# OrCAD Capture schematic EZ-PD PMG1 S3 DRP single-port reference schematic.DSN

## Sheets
1 01. TITLE AND CONTENTS: title: PMG1-S3 (CYPM1311) DRP REFERENCE DESIGN; rev: 01; note: XXX-xxxxx-xx
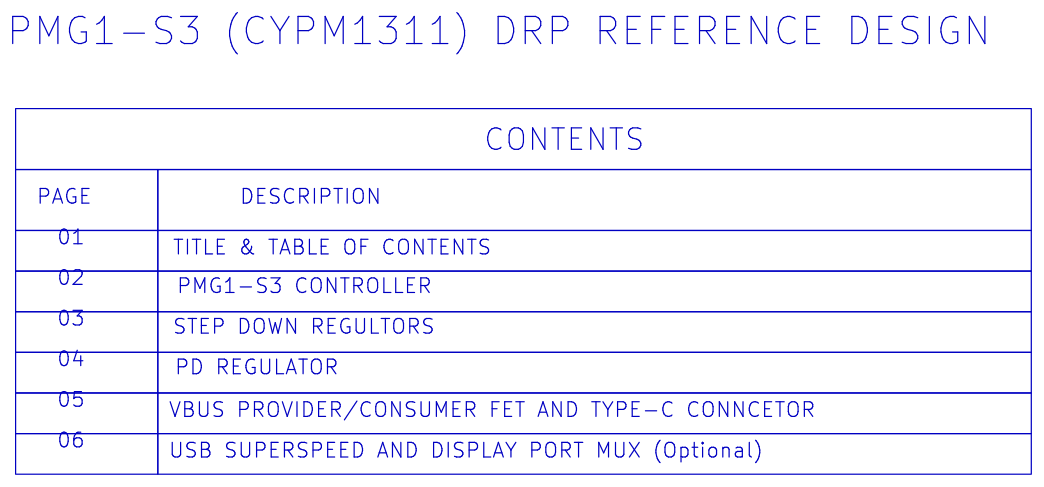
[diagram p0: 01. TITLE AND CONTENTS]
2 05. PROVIDER AND CONSUMER PATH: size A4
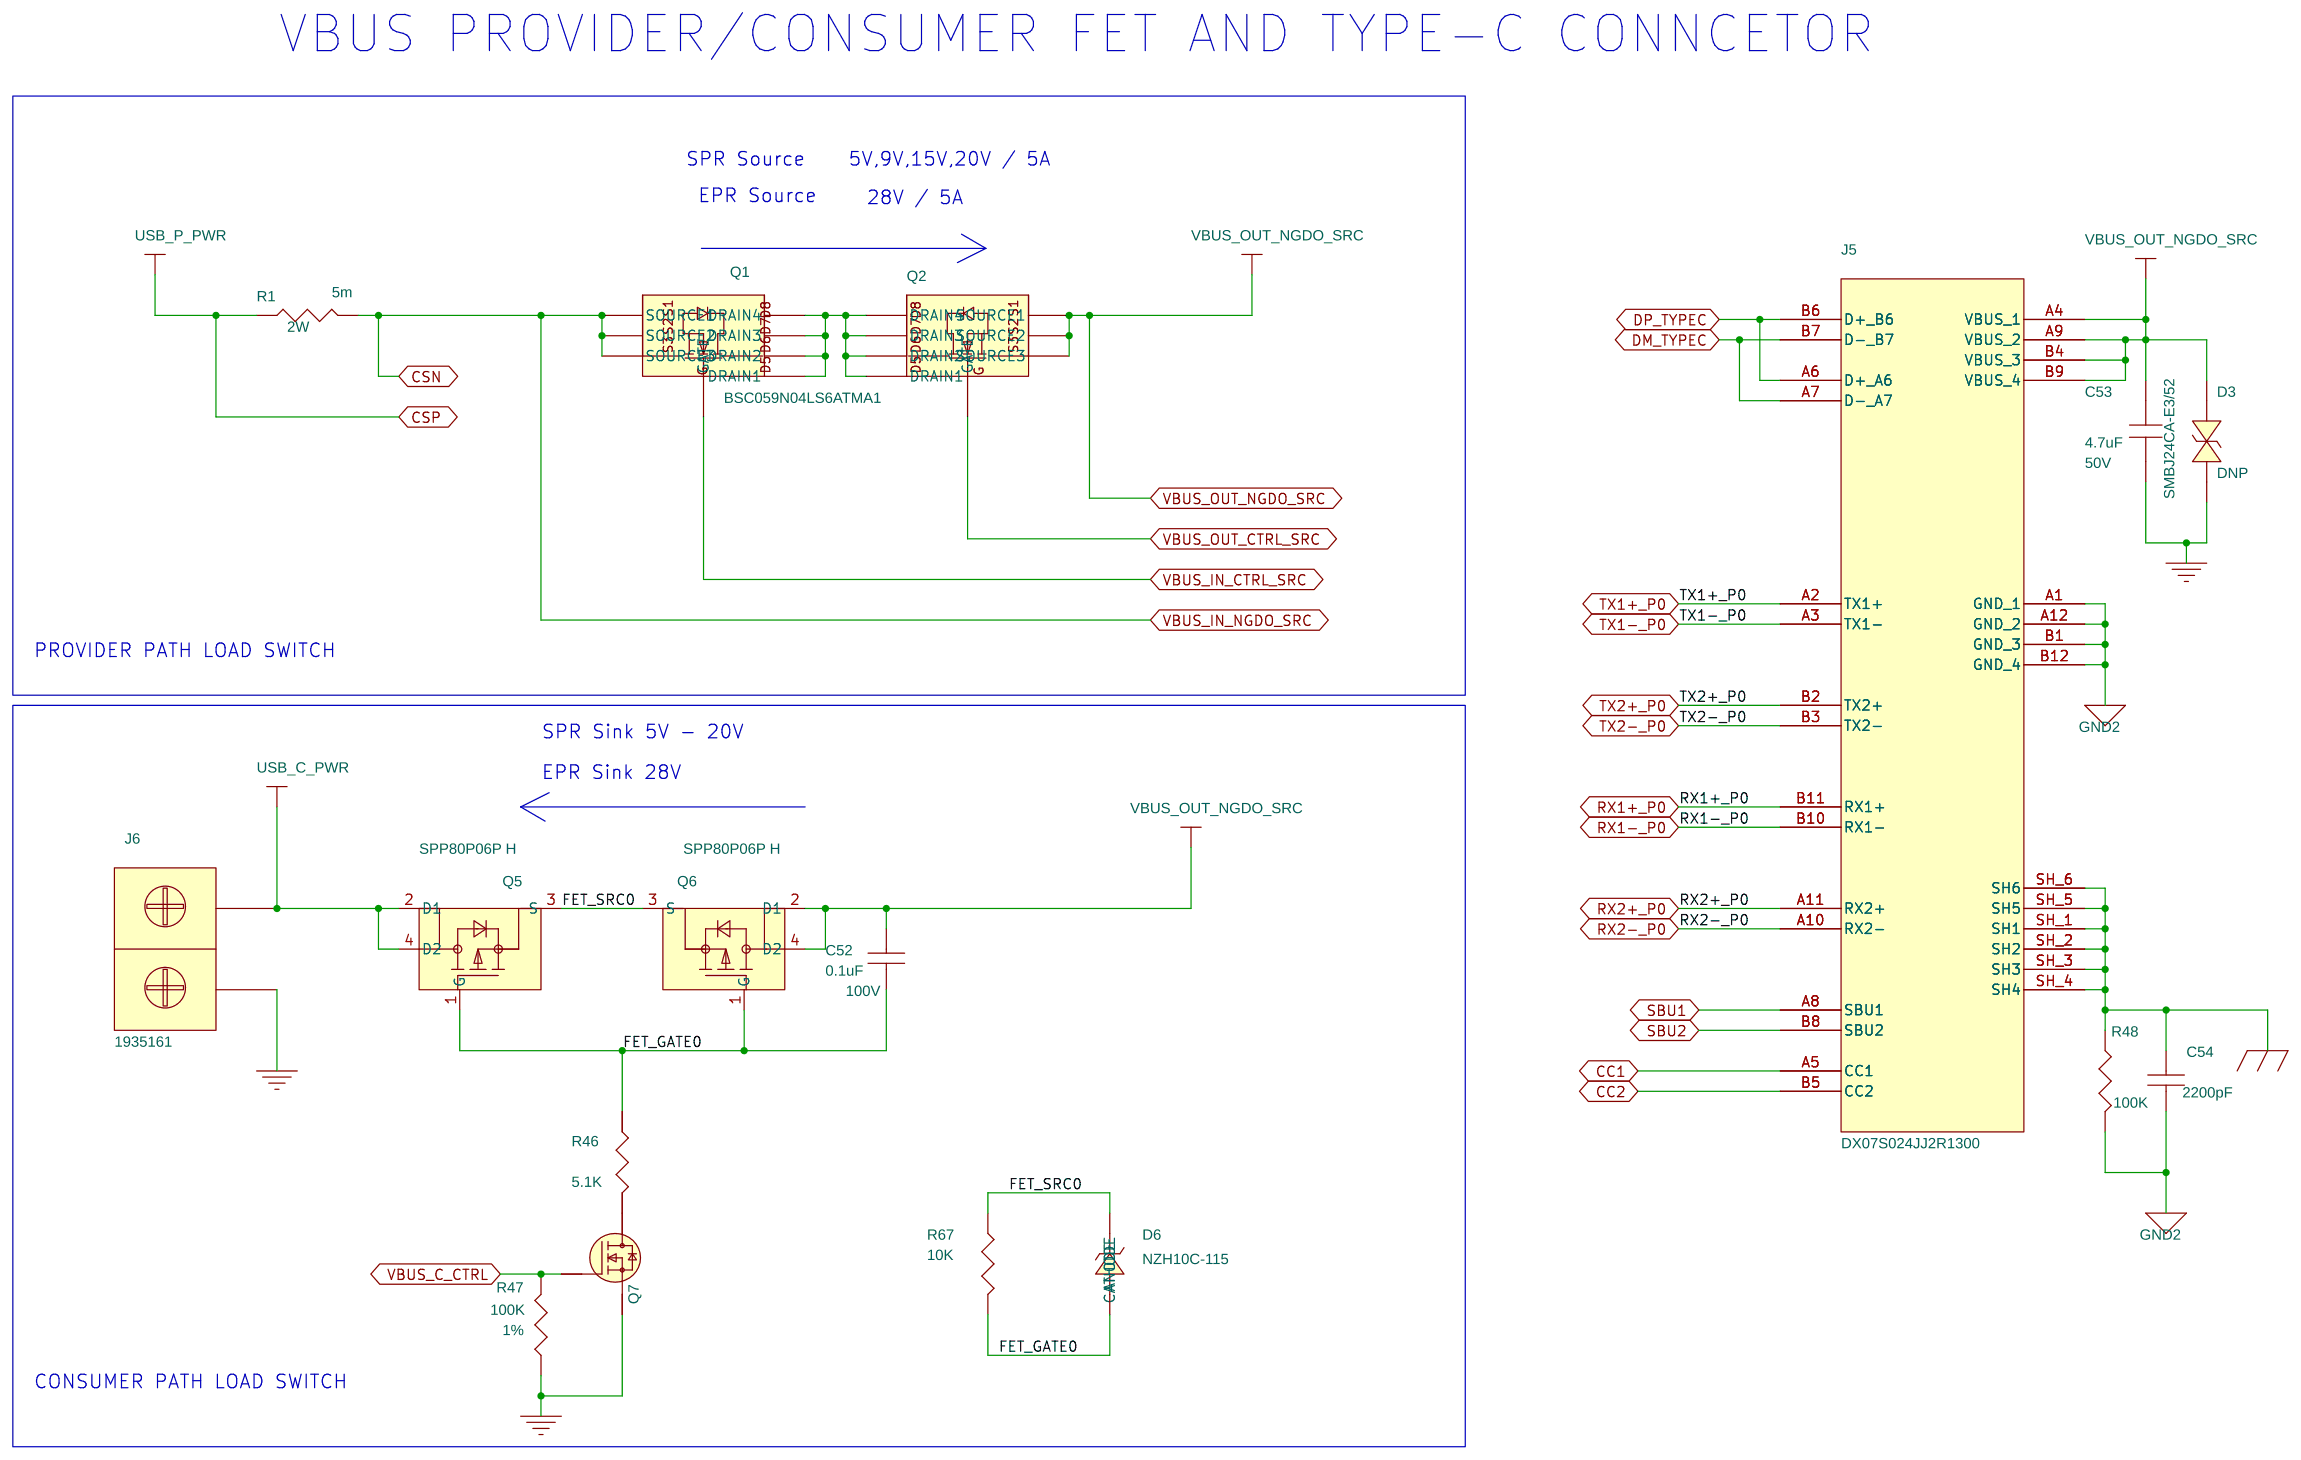
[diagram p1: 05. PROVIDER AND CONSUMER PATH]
3 06. USB SUPERSPEED AND DISPLAY: size A4
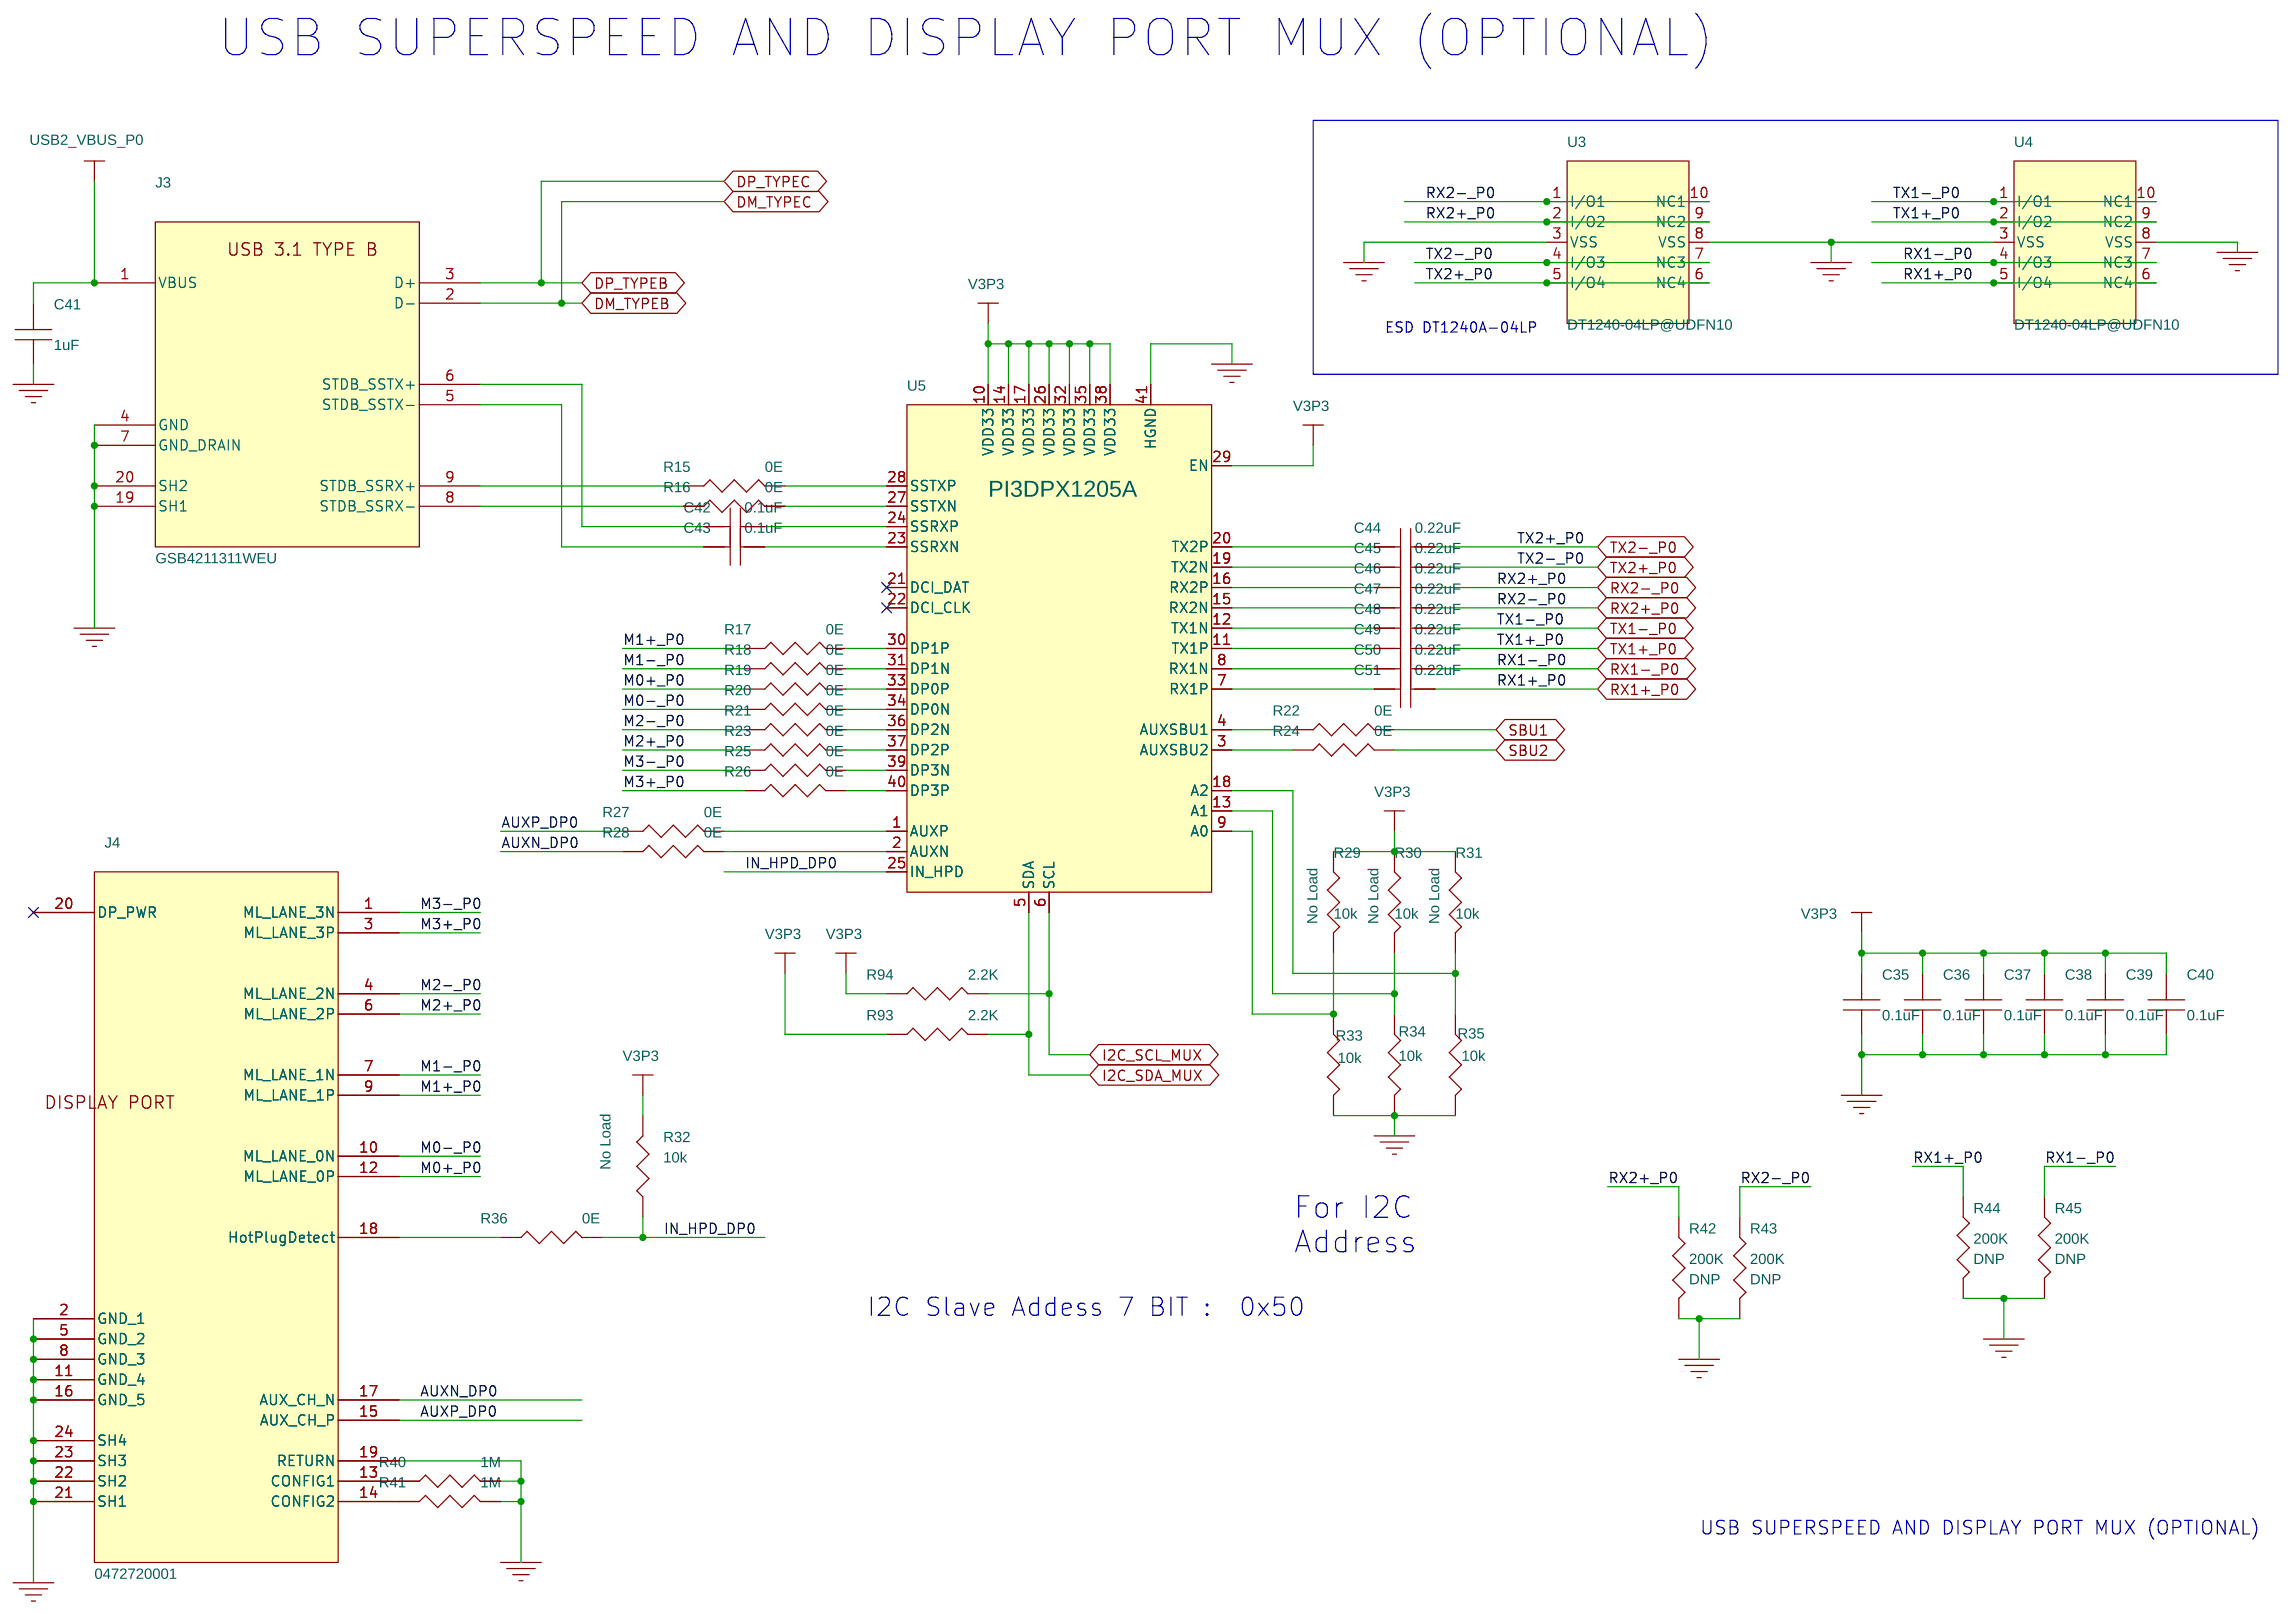
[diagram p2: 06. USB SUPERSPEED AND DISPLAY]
4 04. PD REGULATOR: size A4
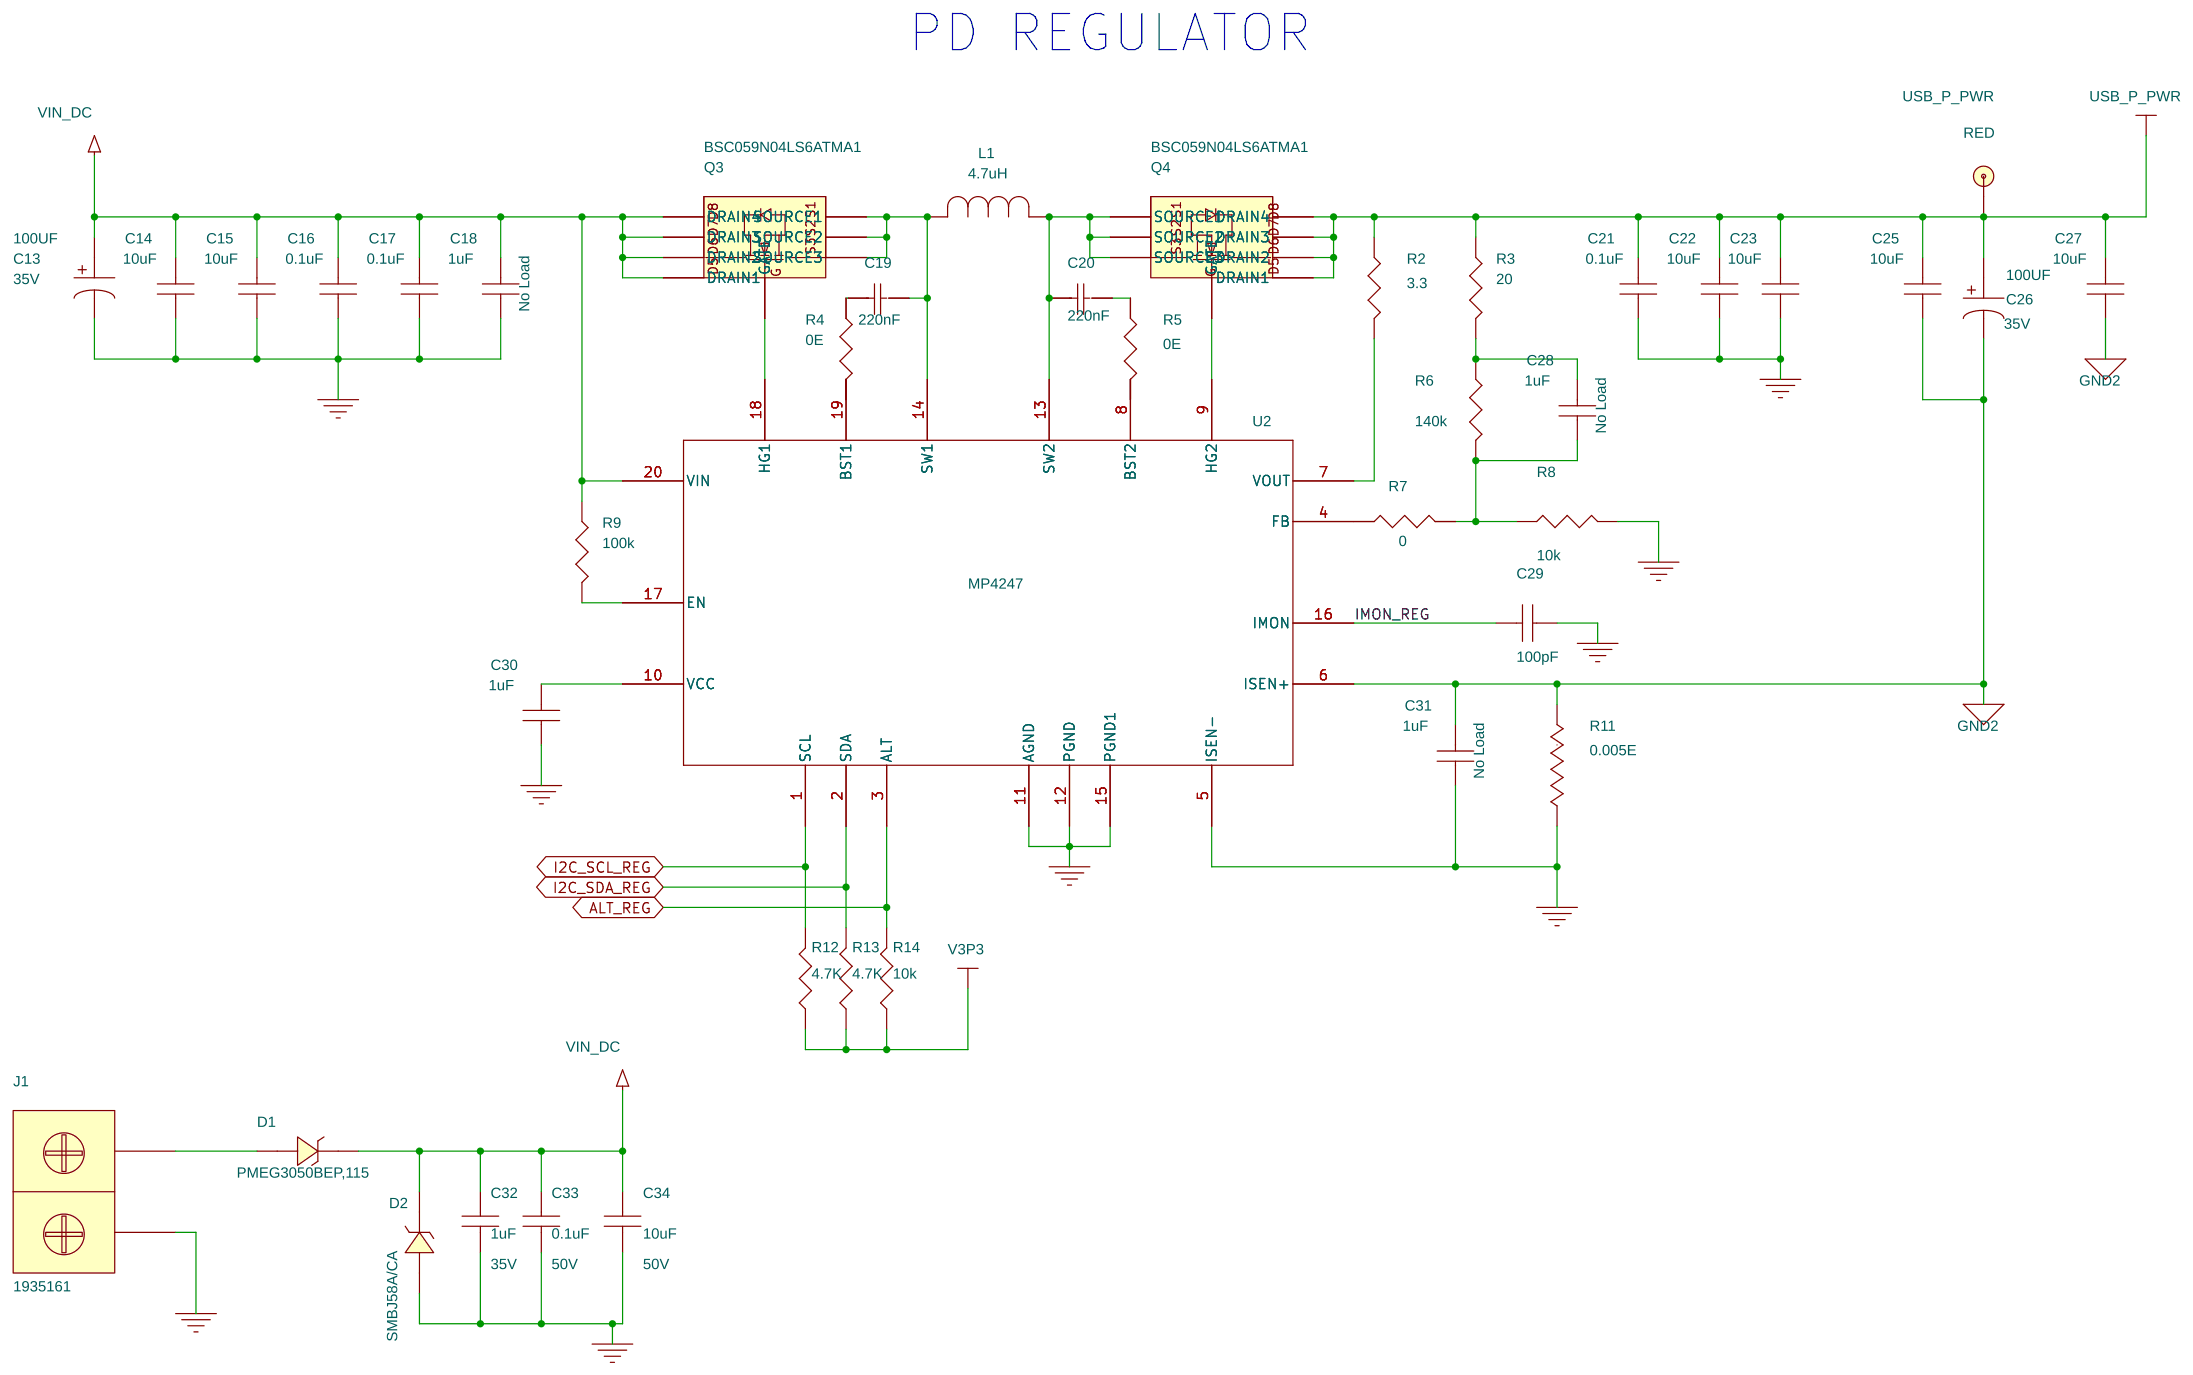
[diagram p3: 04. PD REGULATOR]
5 03. STEP DOWN REGULATORS: size A4
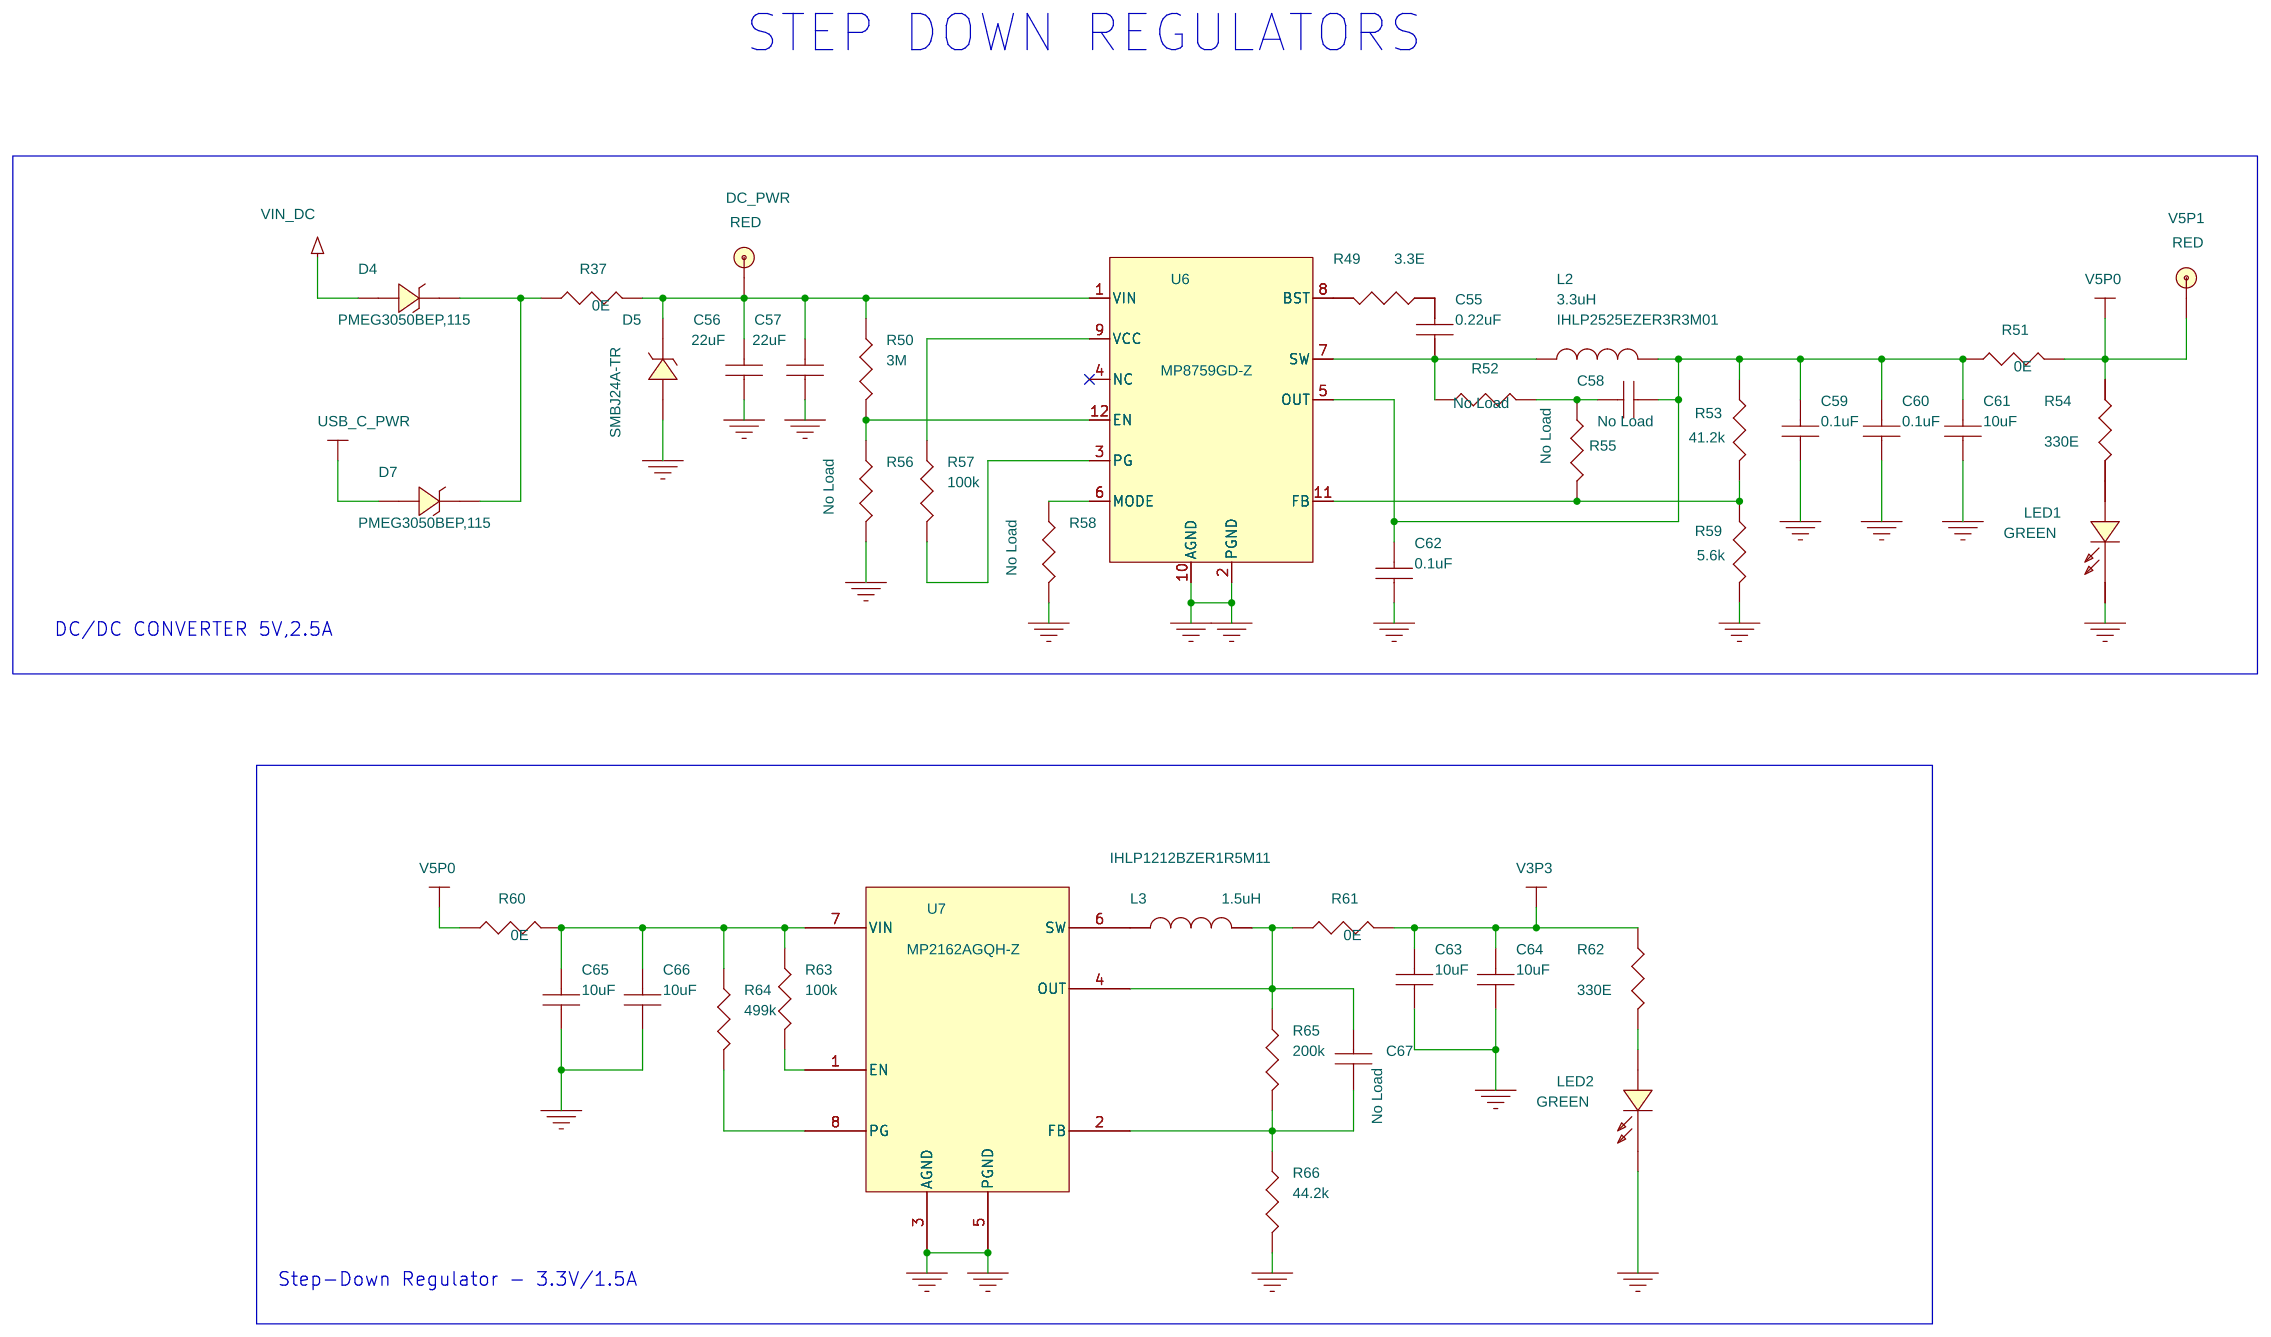
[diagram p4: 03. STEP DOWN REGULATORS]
6 02. PMG1-S3: size A4
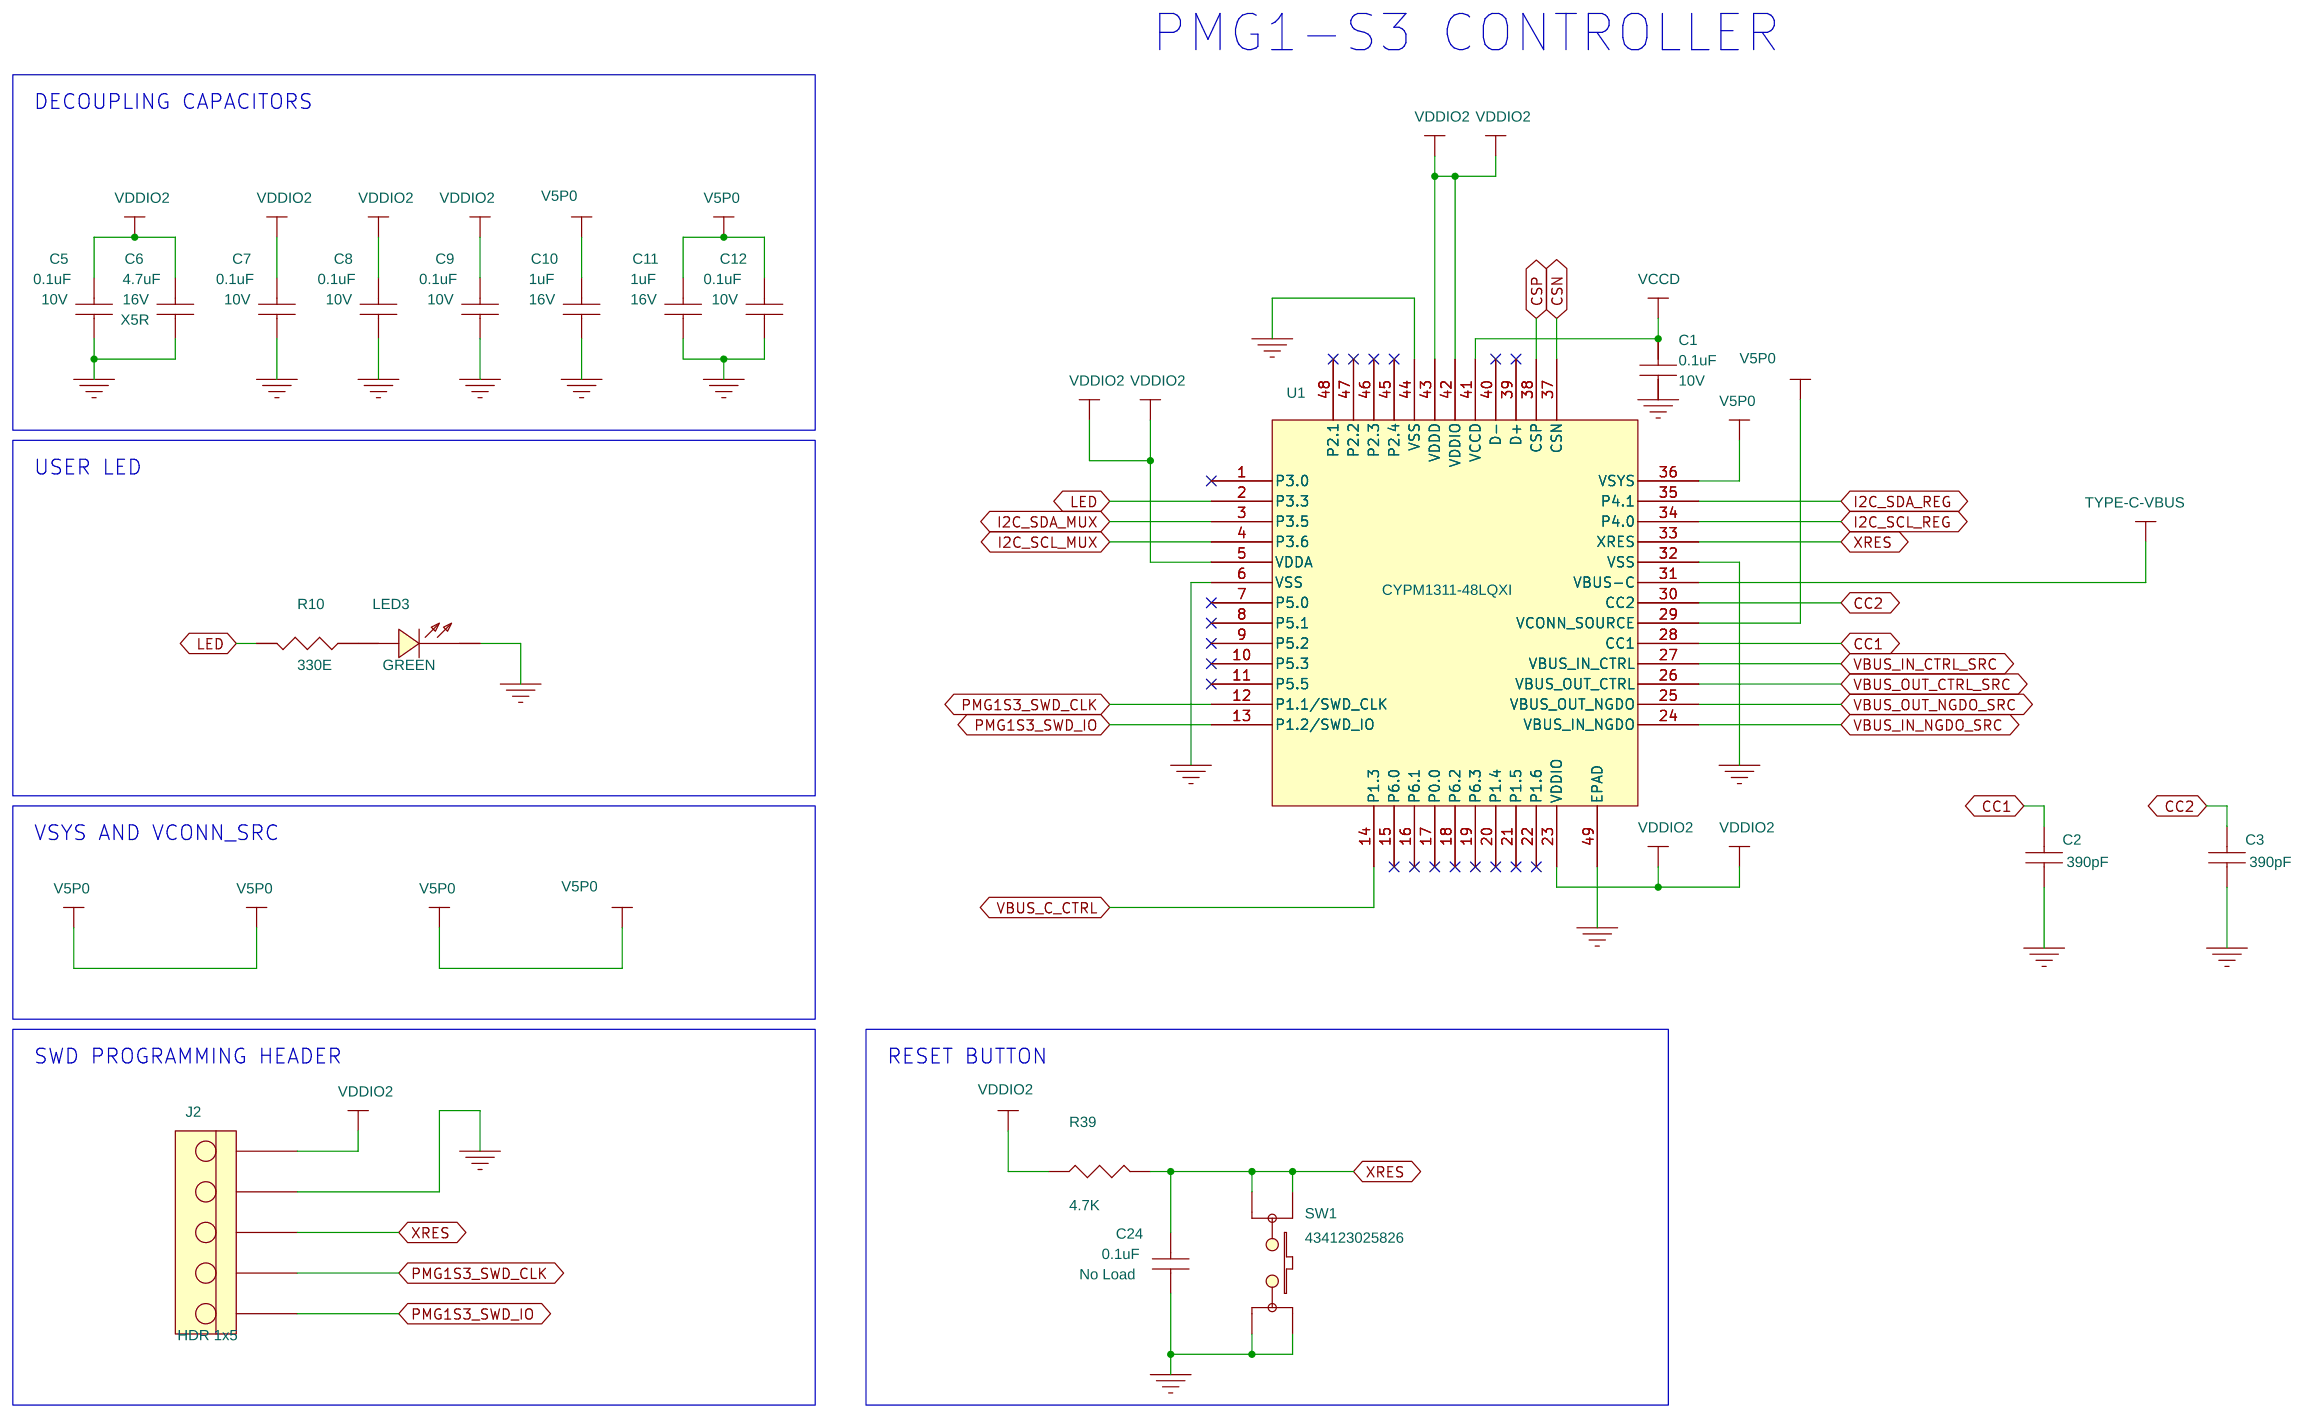
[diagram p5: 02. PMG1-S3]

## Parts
sheet 02. PMG1-S3
C1  0.1uF  [CAPC1005_0402N]
C2  390pF  [capc1608x90n_ty]
C3  390pF  [capc1608x90n_ty]
C5  0.1uF  [CAPC1005_0402N]
C6  4.7uF  [capc1608x90n_ty]
C7  0.1uF  [CAPC1005_0402N]
C8  0.1uF  [CAPC1005_0402N]
C9  0.1uF  [CAPC1005_0402N]
C10  1uF  [capc1608x90n_ty]
C11  1uF  [capc1608x90n_ty]
C12  0.1uF  [CAPC1005_0402N]
C24  0.1uF  [CAPC1005_0402N]
J2  HDR 1x5  [HDR5_KEYED_M]
LED3  GREEN  [LEDC1608X80N_G]
R10  330E  [RESC1608X55N_A]
R39  4.7K  [RESC1005_0402M]
SW1  434123025826  [SW_SKRPACE010]
U1  CYPM1311-48LQXI  [QFN40P600X600X60-49N]
sheet 03. STEP DOWN REGULATORS
C55  0.22uF  [capc1608x90n_ty]
C56  22uF  [CAPC3216X180N]
C57  22uF  [CAPC3216X180N]
C58  0.22uF  [capc1608x90n_ty]
C59  0.1uF  [capc1608x90n_ty]
C60  0.1uF  [capc1608x90n_ty]
C61  10uF  [capc1608x90n_ty]
C62  0.1uF  [capc1608x90n_ty]
C63  10uF  [capc1608x90n_ty]
C64  10uF  [capc1608x90n_ty]
C65  10uF  [capc1608x90n_ty]
C66  10uF  [capc1608x90n_ty]
C67  0.22uF  [capc1608x90n_ty]
D4  PMEG3050BEP,115  [SOD128]
D5  SMBJ24A-TR  [SMBJ24A-TR]
D7  PMEG3050BEP,115  [SOD128]
DC_PWR  RED  [TP-43R_S]
L2  3.3uH  [IHLP2525EZER3R3M01]
L3  1.5uH  [IHLP1212BZER1R5M11]
LED1  GREEN  [LEDC1608X80N_G]
LED2  GREEN  [LEDC1608X80N_G]
R37  0E  [RESC2012X70N_PEC]
R49  3.3E  [resc1608x55n_pec]
R50  3M  [resc1005x40n_pec]
R51  0E  [RESC2012X70N_PEC]
R52  0E  [resc1608x55n_pec]
R53  41.2k  [resc1608x55n_pec]
R54  330E  [resc1608x55n_pec]
R55  0E  [resc1608x55n_pec]
R56  R  [resc1005x40n_pec]
R57  100k  [resc1005x40n_pec]
R58  R  [resc1005x40n_pec]
R59  5.6k  [resc1608x55n_pec]
R60  0E  [RESC2012X70N_PEC]
R61  0E  [RESC2012X70N_PEC]
R62  330E  [resc1608x55n_pec]
R63  100k  [resc1005x40n_pec]
R64  499k  [resc1005x40n_pec]
R65  200k  [resc1005x40n_pec]
R66  44.2k  [resc1005x40n_pec]
U6  MP8759GD-Z  [QFN12_2X3mm]
U7  MP2162AGQH-Z  [QFN8_2P0X1P5]
V5P1  RED  [TP-43R_S]
sheet 04. PD REGULATOR
C13  100UF  [CAPAE830X900D900DD320N]
C14  10uF  [capc1608x90n_ty]
C15  10uF  [capc1608x90n_ty]
C16  0.1uF  [capc1608x90n_ty]
C17  0.1uF  [capc1608x90n_ty]
C18  1uF  [capc1608x90n_ty]
C19  CAP\0603  [CAP_0402]
C20  CAP\0603  [CAP_0402]
C21  0.1uF  [capc1608x90n_ty]
C22  10uF  [capc1608x90n_ty]
C23  10uF  [capc1608x90n_ty]
C25  10uF  [capc1608x90n_ty]
C26  100UF  [CAPAE830X900D900DD320N]
C27  10uF  [capc1608x90n_ty]
C28  1uF  [capc1608x90n_ty]
C29  100pF  [capc1608x90n_ty]
C30  1uF  [capc1005x56n_cyps]
C31  1uF  [capc1608x90n_ty]
C32  1uF  [capc1608x90n_ty]
C33  0.1uF  [capc1005x56n_cyps]
C34  10uF  [capc3225x280n_tdk]
D1  PMEG3050BEP,115  [SOD128]
D2  SMBJ58A/CA  [SMBJ24A-TR]
J1  1935161  [1935161]
L1  TOKO106C_L1  [inductor_adjust]
Q3  BSC059N04LS6ATMA1  [BSC059N04LS6ATMA1]
Q4  BSC059N04LS6ATMA1  [BSC059N04LS6ATMA1]
R2  3.3  [resc1005x40n_pec]
R3  20  [resc1608x55n_pec]
R4  0E  [resc1005x40n_pec]
R5  0E  [resc1005x40n_pec]
R6  140k  [resc1608x55n_pec]
R7  0  [resc1608x55n_pec]
R8  10k  [resc1608x55n_pec]
R9  100k  [resc1608x55n_pec]
R11  0.005E  [WSL1206]
R12  4.7K  [resc1608x55n_pec]
R13  4.7K  [resc1608x55n_pec]
R14  10k  [resc1608x55n_pec]
U2  MP4247  [QFN20]
USB_P_PWR  RED  [TP-43R_S]
sheet 05. PROVIDER AND CONSUMER PATH
C52  0.1uF  [capc1005x56n_cyps]
C53  4.7uF  [capc3225x280n_tdk]
C54  2200pF  [C1808]
D3  SMBJ24CA-E3/52  [SMBJ24CA_3P679_2H44]
D6  NZH10C-115  [SOD123F_NZH10C-115]
J5  DX07S024JJ2R1300  [USB-PD_TYPE-C]
J6  1935161  [1935161]
Q1  BSC059N04LS6ATMA1  [BSC059N04LS6ATMA1]
Q2  BSC059N04LS6ATMA1  [BSC059N04LS6ATMA1]
Q5  SPP80P06P H
Q6  SPP80P06P H
Q7  2N7002LT1G  [SOT23_2N7002LT1G]
R1  5m  [RESC6432X69N]
R46  5.1K  [resc1005x40n_pec]
R47  100K  [resc1608x55n_pec]
R48  100K  [resc1005x40n_pec]
R67  10K  [resc1005x40n_pec]
sheet 06. USB SUPERSPEED AND DISPLAY
C35  0.1uF  [capc1005x56n_cyps]
C36  0.1uF  [capc1005x56n_cyps]
C37  0.1uF  [capc1005x56n_cyps]
C38  0.1uF  [capc1005x56n_cyps]
C39  0.1uF  [capc1005x56n_cyps]
C40  0.1uF  [capc1005x56n_cyps]
C41  1uF  [capc1005x56n_cyps]
C42  0.1uF  [capc1005x56n_cyps]
C43  0.1uF  [capc1005x56n_cyps]
C44  0.22uF  [capc1005x56n_cyps]
C45  0.22uF  [capc1005x56n_cyps]
C46  0.22uF  [capc1005x56n_cyps]
C47  0.22uF  [capc1005x56n_cyps]
C48  0.22uF  [capc1005x56n_cyps]
C49  0.22uF  [capc1005x56n_cyps]
C50  0.22uF  [capc1005x56n_cyps]
C51  0.22uF  [capc1005x56n_cyps]
J3  GSB4211311WEU  [USB_CONN_GSB3211311WEU]
J4  0472720001  [CONN20_0472720001]
R15  0E  [resc1005x40n_pec]
R16  0E  [resc1005x40n_pec]
R17  0E  [resc1005x40n_pec]
R18  0E  [resc1005x40n_pec]
R19  0E  [resc1005x40n_pec]
R20  0E  [resc1005x40n_pec]
R21  0E  [resc1005x40n_pec]
R22  0E  [resc1005x40n_pec]
R23  0E  [resc1005x40n_pec]
R24  0E  [resc1005x40n_pec]
R25  0E  [resc1005x40n_pec]
R26  0E  [resc1005x40n_pec]
R27  0E  [resc1005x40n_pec]
R28  0E  [resc1005x40n_pec]
R29  10k  [resc1608x55n_pec]
R30  10k  [resc1608x55n_pec]
R31  10k  [resc1608x55n_pec]
R32  10k  [resc1005x40n_pec]
R33  10k  [resc1608x55n_pec]
R34  10k  [resc1608x55n_pec]
R35  10k  [resc1608x55n_pec]
R36  0E  [resc1608x55n_pec]
R40  1M  [resc1005x40n_pec]
R41  1M  [resc1005x40n_pec]
R42  200K  [RESC1005X40N_PEC]
R43  200K  [RESC1005X40N_PEC]
R44  200K  [RESC1005X40N_PEC]
R45  200K  [RESC1005X40N_PEC]
R93  2.2K  [RESC2012X70N_PEC]
R94  2.2K  [RESC2012X70N_PEC]
U3  DT1240-04LP@UDFN10  [DT1240-04LP-7_10DFN]
U4  DT1240-04LP@UDFN10  [DT1240-04LP-7_10DFN]
U5  PI3DPX1205A  [QFN40P400X600X80-41T475X275N]

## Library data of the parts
C1 C5 C7-C9 C12 = CAP_NP: CAP CER 0.1UF 10V X7R 0402; Manufacturer: AVX Corporation; Mfr_Name: AVX Corporation; Mfr_Part#: 0402ZC104KAT2A; RATED_VOLTAGE: 10V; Rating: 10V; SIGNAL_MODEL: DEFAULT_CAPACITOR_1pF_1_2; Temp_Coefficient: X7R; Tolerance: 10%; VOLTAGE: 10V
C2 C3 = CAP-NP_0: CAP CER 390PF 50V 5% X7R 0603; Manufacturer: Kemet; Mfr_Name: Kemet; Mfr_Part#: C0603C391J5RACTU; RATED_VOLTAGE: 10V; Temp_Coefficient: X7R; Tolerance: 5%; VOLTAGE: 50V
C6 = CAP-NP_0: CAP CER 4.7UF 16V X5R 0603; Manufacturer: Samsung Electro-Mechanics; Mfr_Name: Samsung Electro-Mechanics; Mfr_Part#: CL10A475KO8NNNC; RATED_VOLTAGE: 16V; Temp_Coefficient: X5R; Tolerance: 10%; VOLTAGE: 16V
C10 C11 = CAP-NP_0: CAP CER 1UF 16V X7R 0603; Manufacturer: KEMET; Mfr_Name: KEMET; Mfr_Part#: C0603C105K4RACTU; RATED_VOLTAGE: 16V; Temp_Coefficient: X7R; Tolerance: 10%; VOLTAGE: 16V
C24 = CAPACITOR_NON-POL: CAP CER 0.1UF 16V X7R 0402; Asm_Instruction: No Load; Cy_Part#: 510-60247-01; Manufacturer: Würth Elektronik; Mfr_Name: Wurth; Mfr_Part#: 885012205037; Tolerance: 10%; VOLTAGE: 16V
J2 = 1X5_100MIL_HDR_4: CONN HEADER 5POS 0.1 VERT KEYED; MFG Part number: 22232051; Manufacturer: Molex, LLC; Mfr_Name: Molex; Mfr_Part#: 22232051; Mfr_Part_Number: 22-23-2051; PART_NUMBER: 22232051
LED3 = LED_GREEN2_0603: LED GREEN CLEAR 0603 SMD; Manufacturer: Lite-On Inc.; Manufacturer Part Num: 160-1183-6-ND; Mfr_Name: Lite-On Inc.; Mfr_Part#: LTST-C190GKT
R10 = RESD,0402,5%,1_32W,10K: RES SMD 330 OHM 5% 1/10W 0603; IPN: D66113-001; Manufacturer: Yageo; Mfg2: Yageo; Mfr_Name: Yageo; Mfr_Part#: RC0603JR-07330RL; Tolerance: 5%; Wattage: 1/10W
R39 = RESISTOR: RES, 4.7K OHM, 5%, 100PPM, 1/16W, 0402; Cy_part#: 500-60095-01; Manufacturer: Yageo; Mfr_Name: Yageo; Mfr_Part#: RC0402JR-074K7L; Tolerance: 5%
SW1 = SW_PUSH_NO_4-PIN: SW, TACTILE SWITCH, 4.2x3.2x2.5MM, 260GF; Cy_part#: 770-60033-01; Manufacturer: Würth Elektronik; Mfr_Name: Wurth
U1 = CYPM1311-48LQXI_0: Manufacturer: CYPRESS; Mfr_Name: CYPRESS
C55 = CAP-NP_0: CAP CER 0.22UF 10V X7R 0603; Manufacturer: YAGEO; Mfr_Part#: CC0603KRX7R6BB224
C56 C57 = CAP-NP_0: CAP CER 22UF 35V X5R 1206; Manufacturer: TDK Corporation; Mfr_Part#: C3216X5R1V226M160AC
C58 C67 = CAP-NP_0: CAP CER 0.22UF 10V X7R 0603; Asm_Instruction: No Load; Manufacturer: YAGEO; Mfr_Part#: CC0603KRX7R6BB224
C16 C17 C21 C59 C60 C62 = CAP-NP_0: CAP CER 0.1UF 10V X7R 0603; Manufacturer: Kemet; Mfr_Part#: C0603C104K8RACTU
C14 C15 C22 C23 C25 C27 C61 C63-C66 = CAP-NP_0: CAP CER 10UF 10V 10% X5R 0603; Manufacturer: TDK Corporation; Mfr_Part#: C1608X5R1A106K080AC
D1 D4 D7 = BZX84C18_SOT_0: DIODE SCHOTTKY 30V 5A SOD128; Cypress Part No: 530-60089-01; Manufacturer: NXP Semiconductors
D2 D5 = BZX84C18_SOT_0: TVS DIODE 24VWM 50VC DO214AA; Cypress Part No: 530-60092-01; Manufacturer: STMicroelectronics
DC_PWR USB_P_PWR V5P1 = TEST_POINT: TEST POINT PC MINI .040"D RED; Cypress Part No: 711-60001-01; Manufacturer: Keystone Electronics; Mfr_Part#: 5001
L2 = INDUCTOR: FIXED IND 3.3UH 8A 20.9 MOHM SMD; Cost: .01; Manufacturer: Vishay Dale; Tolerance: NA; Voltage: NA
L3 = INDUCTOR: FIXED IND 1.5UH 3.8A 32 mOHM SMD; Cost: .01; Manufacturer: Vishay Dale; Tolerance: NA; Voltage: NA
LED1 LED2 = LED_GREEN2_0: LED GREEN CLEAR 0603 SMD; Cypress Part No: 534-60005-01; MFG Part number: LTST-C190GKT; Manufacturer: Lite-On Inc.; Mfr_Part#: LTST-C190GKT
R37 R51 R60 R61 = R: RES 0 OHM JUMPER 1/8W 0805; Manufacturer: YAGEO; Mfr_Part#: RC0805JR-070RL
R49 = R: RES SMD 3.3 OHM 5% 1/10W 0603; Manufacturer: Panasonic Electronic Components; Mfr_Part#: ERJ-3GEYJ3R3V
R50 = R: RES 3M OHM 5% 1/16W 0402; Manufacturer: YAGEO; Mfr_Part#: RC0402JR-073ML
R52 R55 = R: RES 0 OHM JUMPER 1/10W 0603; Asm_Instruction: No Load; Manufacturer: YAGEO; Mfr_Part#: RC0603FR-070RL
R53 = R: RES 41.2K OHM 1% 1/10W 0603; Manufacturer: YAGEO; Mfr_Part#: RC0603FR-0741K2L
R54 R62 = R: RES SMD 330 OHM 5% 1/10W 0603; Manufacturer: YAGEO; Mfr_Name: YAGEO; Mfr_Part#: RC0603JR-07330RL; Wattage: 1/10W
R56 R58 = R: Asm_Instruction: No Load
R57 R63 = R: RES SMD 100K OHM 1% 1/5W 0402; MFG Part number: RCS0402100KFKED; Manufacturer: Vishay Dale; Mfr_Part#: RCS0402100KFKED
R59 = R: RES 5.6K OHM 5% 1/10W 0603; Manufacturer: YAGEO; Mfr_Part#: RC0603JR-075K6L
R64 = R: RES 499K OHM 0.1% 1/16W 0402; Manufacturer: YAGEO; Mfr_Part#: RC0402BR-07499KL
R65 = R: RES SMD 200K OHM 1% 1/10W 0402; MFG Part number: ERJ-2RKF2003X; Manufacturer: Panasonic Electronic Components; Mfr_Part#: ERJ-2RKF2003X
R66 = R: RES 44.2K OHM 1% 1/16W 0402; Manufacturer: YAGEO; Mfr_Part#: RC0402FR-0744K2L
U6 = mp8759_0: IC SYNC BUCK CONVERTER 8A 26V; Manufacturer: MPS
U7 = MP2162_1: IC REG BUCK ADJ 2A SYNC QFN; Manufacturer: MPS
C13 C26 = CAP_TH_Rad_8mmDia_3_5mmPitch: CAP ALUM POLY 100UF 20% 35V SMD; MFG Part number: RHS1V101MCN1GS; Manufacturer: Nichicon; Mfr_Name: Nichicon; Mfr_Part#: RHS1V101MCN1GS; Voltage: 35V
C18 C28 C31 = CAP-NP_0: CAP CER 1UF 35V X7R 0603; Asm_Instruction: No Load; Manufacturer: TDK Corporation; Mfr_Part#: C1608X7R1V105K080AC
C19 = CAP0603_C3: User_Value: 220nF
C20 = CAP0603_C4: User_Value: 220nF
C29 = CAP-NP_0: CAP CER 100PF 50V C0G 0603; Manufacturer: TDK Corporation; Mfr_Part#: C1608C0G1H101J080AA
C30 = CAP-NP_0: CAP CER 0.1UF 10V X7R 0402; Alternate Manufacturer: Samsung Electro-Mechanics; Alternate Mfr Part #: CL05B104KP5NNNC; Manufacturer: TDK Corporation; Mfr_Part#: C1005X7R1A104K050BB
C32 = CAP_NP: CAP CER 1UF 35V X7R 0603; Cypress Part No: 510-60420-01; MFG Part number: C1608X7R1V105K080AC; Manufacturer: TDK Corporation; Mfr_Part#: C1608X7R1V105K080AC; VOLTAGE: 35V
C33 = CAP_NP: CAP CER 0.1UF 25V X7R 0402; Alternate Manufacturer: Samsung Electro-Mechanics; Alternate Mfr Part #: CL05B104KP5NNNC; Manufacturer: TDK Corporation; Mfr_Part#: C1005X7R1H104K050BB; Voltage: 50V
C34 = CAP_NP: CAP CER 10UF 50V X7R 1210; Cypress Part No: 510-60333-01; MFG Part number: CL32B106KBJNNWE; Manufacturer: Samsung Electromechanics; Mfr Prt #: CL32B106KBJNNWE; Mfr_Part#: CL32B106KBJNNWE; VOLTAGE: 50V
J1 J6 = TERMINAL_BLOCK: TERM BLOCK PCB 2POS 5.0MM GREEN; Cypress Part No: 720-60276-01; Manufacturer: Phoenix Contact
L1 = TOKO106C_L1: User_Value: 4.7uH
Q1-Q4 = BSC059N04LS_G_2: MOSFET N-CH 40V 17A TDSON; Manufacturer: Infineon Technologies; Mfr_Name: Infineon Technologies
R2 = RESISTOR: RES SMD 3.3 OHM 1% 1/16W 0402; DIGI-KEY PART NO: 541-0.0JCT-ND; MFG Part number: CRCW04023R30FKED; Manufacturer: Vishay Dale; Manufaturer: Vishay Dale; Mfr_Part#: CRCW04023R30FKED; Price: 0.074
R3 = R: RES SMD 20 OHM 5% 1/10W 0603; Manufacturer: Vishay Dale; Mfr_Part#: CRCW060320R0JNEA
R4 R5 = RESISTOR: RES 0.0 OHM 1/16W JUMP 0402 SMD; DIGI-KEY PART NO: 541-0.0JCT-ND; MFG Part number: CRCW04020000Z0ED; Manufacturer: Vishay Dale; Mfr_Part#: CRCW04020000Z0ED; Price: 0.074
R6 = R: RES 140K OHM 1% 1/10W 0603; Manufacturer: YAGEO; Mfr_Part#: RC0603FR-07140KL
R7 R36 = R: RES 0 OHM JUMPER 1/10W 0603; Manufacturer: YAGEO; Mfr_Part#: RC0603FR-070RL
R8 R14 R33-R35 = R: RES 10K OHM 5% 1/10W 0603; Manufacturer: YAGEO; Mfr_Part#: RC0603JR-1010KL
R9 = R: RES SMD 100K OHM 1% 1/10W 0603; MFG Part number: ERJ-3EKF1003V; Manufacturer: PANASONIC ELECTRONIC COMPONENTS; Mfr_Part#: ERJ-3EKF1003V
R11 = Resistor_1206_Generic_SMD_4: 0.005 Ohms 1 %  1/2 W 1206 SMD; MFG: Vishay; MFG Part number: WSL12065L000FEA18; Manufacturer: Vishay Dale; Mfr_Part#: WSL12065L000FEA18; Package: 1206; Wattage: 1/2 W
R12 R13 = R: RES 4.7K OHM 5% 1/10W 0603; Manufacturer: RC0603JR-074K7L; Mfr_Part#: RC0603JR-074K7L
U2 = MPQ4260_U1_0: Buck-boost converter with lowside MOSFETs; MFG Part number: MP4247GQV; Manufacturer: Monolithic Power Systems; Mfr_Part#: MP4247GQV
C52 = CAP_NP: CAP CER 0.1UF 25V X7R 0402; Alternate Manufacturer: Samsung Electro-Mechanics; Alternate Mfr Part #: CL05B104KP5NNNC; Manufacturer: TDK Corporation; Mfr_Part#: C1005X7R1A104K050BB; Voltage: 100V
C53 = 10uF-50V-10%-X5R-1206: CAP CER 4.7UF 50V X7R 1210; Cypress Part No: 510-60425-01; MFG Part number: GRJ32ER71H475KE11L; Manufacturer: Murata Electronics North America; Mfr_Part#: GRJ32ER71H475KE11L; Voltage: 50V
C54 = CAP_NP: CAP CER 2200PF 2KV 10% X7R 1808; Cypress Part No: 510-60319-01; MFG Part number: 202R29W222KV4E; Manufacturer: Johanson Dielectrics Inc.; Mfr_Part#: 202R29W222KV4E; Tolerance: 10%; VOLTAGE: 2KV
D3 = BZX84C18_SOT_1: TVS DIODE 24V 38.9V DO214AA; Cypress Part No: 530-60094-01; DNP: DNP; Manufacturer: Vishay Semiconductor Diodes Division
D6 = DIODE_ZENER: DIODE ZENER 10V 500MW SOD123F; MFG Part number: NZH10C,115; Manufacturer: Nexperia USA Inc.; Mfr_Name: Nexperia USA Inc.; Mfr_Part#: NZH10C,115
J5 = USB-PD_TYPE-C_20: USB TYP C TP MNT DL RW SMT RECEP; DIGI-KEY PART NO: 670-2794-1-ND; Manufacturer: JAE Electronics; Price: 2.61
Q5 Q6 = SPP80P06P_H_1: MOSFET P-CH 60V 80A TO220-3; Manufacturer: Infineon Technologies
Q7 = N-MOSFET_2N7002_SOT23_0: MOSFET N-CH 60V 0.115A SOT-23; Alternate Manufacturer: ON SEMICONDUCTOR; Alternate Part Number: 2V7002LT3G; Manufacturer: ON SEMICONDUCTOR
R1 = RESISTOR: RES SMD 0.005 OHM 1% 2W 2512; DIGI-KEY PART NO: RHM.010AUCT-ND; MFG Part number: PMR100HZPFU5L0; Manufacturer: Rohm Semiconductor; Mfr_Part#: PMR100HZPFU5L0; Price: 0.77; TOLERANCE: 1%; WATT: 2W
R46 = RESISTOR: RES SMD 5.1K OHM 1% 1/16W 0402; MFG Part number: RC0402FR-075K1L; Manufacturer: Yageo; Mfr_Name: Yageo; Mfr_Part#: RC0402FR-075K1L; Price: 0.1; TOLERANCE: 5%
R47 = 100K-1_16W-5%-0603: RES SMD 100K OHM 1% 1/10W 0603; ALTERNATE PART NUMBER: RMCF0603FT100K; Alternate Manufacturer_1: Yageo America; Alternate Part number_1: RC0603FR-07100KL; MFG Part number: ERJ-3EKF1003V; Manufacturer: PANASONIC ELECTRONIC COMPONENTS; Mfg1_PN: ERJ-3GEYJ104V; Mfr_Part#: ERJ-3EKF1003V; PART_NUMBER: ERJ-3GEYJ104V; Tolerance: 1%; Wattage: 1/10W
R48 = 10K-1_16W-5%-0603: RES SMD 100K OHM 1% 1/5W 0402; Cypress Part No: 500-60075-01; MFG Part number: RCS0402100KFKED; Manufacturer: Vishay Dale; Mfr_Part#: RCS0402100KFKED
R67 = R: RES 10K OHM 5% 1/16W 0402; MFG Part number: RC0402JR-0710KL; Manufacturer: YAGEO; Mfr_Name: YAGEO; Mfr_Part#: RC0402JR-0710KL; Price: 0.1; Tolerance: 5%
C35-C40 C42 C43 = CAP-NP_0: CAP CER 0.1UF 25V X7R 0402; Alternate Manufacturer: Samsung Electro-Mechanics; Alternate Mfr Part #: CL05B104KP5NNNC; Manufacturer: TDK Corporation; Mfr_Part#: C1005X7R1A104K050BB; Voltage: 10V
C41 = CAP-NP_0: CAP CER 0.1UF 10V X7R 0402; Alternate Manufacturer: Samsung Electro-Mechanics; Alternate Mfr Part #: CL05B104KP5NNNC; Manufacturer: TDK Corporation; Mfr_Part#: C1005X7R1A104K050BB; Voltage: 10V
C44-C51 = CAP-NP_0: CAP CER 0.22UF 16V X7R 0402; Manufacturer: Yageo; Mfr_Part#: CC0402KRX7R7BB224; Voltage: 16V
J3 = USB3_TYPE-B_0: Connector Receptacle USB TypeB 3.1, Super Speed 9 Position Through Hole, Right Angle, Horizontal; DIGI-KEY PART NO: GSB4211311WEU-ND; Manufacturer: Amphenol Commercial Products; Price: 2.54
J4 = DISPLAY_PORT_CONN_10: Connector Receptacle DisplayPort 20 Position Surface Mount, Right Angle, Horizontal; DIGI-KEY PART NO: WM19271CT-ND; MFG Part number: 472720001; Manufacturer: Molex, LLC; Mfr_Part#: 472720001; Price: 5.3
R15-R21 R23 R25 R26 = R: RES 0.0 OHM 1/16W JUMP 0402 SMD; Manufacturer: Vishay Dale; Mfr_Part#: CRCW04020000Z0ED
R22 R24 R27 R28 = R: RES 0.0 OHM 1/16W JUMP 0402 SMD; Asm_Instruction: No Load; Manufacturer: Vishay Dale; Mfr_Part#: CRCW04020000Z0ED
R29-R31 = R: RES 10K OHM 5% 1/10W 0603; Asm_Instruction: No Load; Manufacturer: YAGEO; Mfr_Part#: RC0603JR-1010KL
R32 = R: RES 10K OHM 5% 1/16W 0402; Asm_Instruction: No Load; Manufacturer: YAGEO; Mfr_Part#: RC0402JR-0710KL
R40 R41 = R: RES 1M OHM 5% 1/16W 0402; Manufacturer: YAGEO; Mfr_Part#: RC0402JR-071ML
R42-R45 = R: RES SMD 200K OHM 1% 1/10W 0402; DNP: DNP; MFG Part number: ERJ-2RKF2003X; Manufacturer: Panasonic Electronic Components; Mfr_Part#: ERJ-2RKF2003X; Part No.: ERJ-1GEF2003C
R93 R94 = RESD,0402,5%,1_32W,10K: RES SMD 2.2K OHM 5% 1/2W 0805; MFG Part number: ERJ-P6WJ222V; Manufacturer: Panasonic Electronic Components; Mfg1: Panasonic Electronic Components; Mfg1_PN: ERJ-P6WJ222V; Mfr_Name: Panasonic Electronic Components; Mfr_Part#: ERJ-3GEYJ242V; PART_NUMBER: ERJ-P6WJ222V; Part Number: ERJ-P6WJ222V; Tolerance: 5%; Wattage: 0.5W
U3 U4 = DT1240-04LP-UDFN10: TVS DIODE 5.5VWM 11VC DFN; MFG Part Number: DT1240-04LP; Manufacturer: Diodes Incorporated; Mfr_Part#: DT1240-04LP
U5 = PI3DPX1205AZLBE-TQFN40_0: 10G MUX; MFG Part Number: PI3DPX1205AZLBE; Manufacturer: Pericom; Mfr_Part#: PI3DPX1205AZLBE

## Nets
GND: C1.1 C2.1 C3.1 C5.1 C6.1 C7.1 C8.1 C9.1 C10.1 C11.1 C12.1 C13.2 C14.1 C15.1 C16.1 C17.1 C18.1 C21.1 C22.1 C23.1 C24.1 C29.1 C30.1 C31.1 C32.2 C33.2 C34.2 C35.1 C36.1 C37.1 C38.1 C39.1 C40.1 C41.1 C53.1 C56.1 C57.1 C59.1 C60.1 C61.1 C62.1 C63.1 C64.1 C65.1 C66.1 D2.A(ANODE) D3.A(ANODE) D5.A(ANODE) J1.1 J2.2 J3.4(GND) J3.7(GND_DRAIN) J3.19(SH1) J3.20(SH2) J4.2(GND_1) J4.5(GND_2) J4.8(GND_3) J4.11(GND_4) J4.16(GND_5) J4.19(RETURN) J4.21(SH1) J4.22(SH2) J4.23(SH3) J4.24(SH4) J6.2 LED1.K(CATHODE) LED2.K(CATHODE) LED3.K(CATHODE) Q7.2(SOURCE) R8.2 R11.2 R33.2 R34.2 R35.2 R40.2 R41.2 R42.2 R43.2 R44.2 R45.2 R47.1 R56.2 R58.2 R59.2 R66.2 SW1.3 SW1.4 U1.6(VSS) U1.32(VSS) U1.44(VSS) U1.49(EPAD) U2.5(ISEN-) U2.11(AGND) U2.12(PGND) U2.15(PGND1) U3.3(VSS) U3.8(VSS) U4.3(VSS) U4.8(VSS) U5.41(HGND) U6.2(PGND) U6.10(AGND) U7.3(AGND) U7.5(PGND)
GND2: C25.1 C26.2 C27.1 C31.2 C54.2 J5.A1(GND_1) J5.A12(GND_2) J5.B1(GND_3) J5.B12(GND_4) R11.1 R48.2 U2.6(ISEN+)
GND_EARTH1: C54.1 J5.SH_1(SH1) J5.SH_2(SH2) J5.SH_3(SH3) J5.SH_4(SH4) J5.SH_5(SH5) J5.SH_6(SH6) R48.1
V3P3: C35.2 C36.2 C37.2 C38.2 C39.2 C40.2 C63.2 C64.2 R12.1 R13.1 R14.1 R29.1 R30.1 R31.1 R32.2 R61.2 R62.1 R93.1 R94.1 U5.10(VDD33) U5.14(VDD33) U5.17(VDD33) U5.26(VDD33) U5.29(EN) U5.32(VDD33) U5.35(VDD33) U5.38(VDD33)
V5P0: C10.2 C11.2 C12.2 R51.2 R54.1 R60.1 U1.29(VCONN_SOURCE) U1.36(VSYS) V5P1.1
VBUS_C_CTRL: Q7.1(GATE) R47.2 U1.14(P1.3)
VBUS_IN_CTRL_SRC: Q1.4(GATE) U1.27(VBUS_IN_CTRL)
VBUS_OUT_CTRL_SRC: Q2.4(GATE) U1.26(VBUS_OUT_CTRL)
VCCD: C1.2 U1.41(VCCD)
VDDA: C5.2 C6.2 C7.2 C8.2 C9.2 J2.1 R39.2 U1.5(VDDA) U1.23(VDDIO) U1.42(VDDIO) U1.43(VDDD)
VIN_DC: C13.1 C14.2 C15.2 C16.2 C17.2 C18.2 C32.1 C33.1 C34.1 D1.C(CATHODE) D2.C(CATHODE) D4.A(ANODE) Q3.5(DRAIN1) Q3.6(DRAIN2) Q3.7(DRAIN3) Q3.8(DRAIN4) R9.1 U2.20(VIN)
ALT_REG: R14.2 U2.3(ALT)
AUXN_DP0: J4.17(AUX_CH_N) R28.1
AUXP_DP0: J4.15(AUX_CH_P) R27.1
CC1: C2.2 J5.A5(CC1) U1.28(CC1)
CC2: C3.2 J5.B5(CC2) U1.30(CC2)
CSN: Q1.1(SOURCE1) Q1.2(SOURCE2) Q1.3(SOURCE3) R1.2 U1.24(VBUS_IN_NGDO) U1.37(CSN)
DM_TYPEB: J3.2(D-) J5.A7(D-) J5.B7(D-)
DP_TYPEB: J3.3(D+) J5.A6(D+) J5.B6(D+)
FET_GATE0: C52.2 D6.2(ANODE) Q5.1(G) Q6.1(G) R46.1 R67.2
FET_SRC0: D6.1(CATHODE) Q5.3(S) Q6.3(S) R67.1
I2C_SCL_MUX: R94.2 U1.4(P3.6) U5.6(SCL)
I2C_SCL_REG: R12.2 U1.34(P4.0) U2.1(SCL)
I2C_SDA_MUX: R93.2 U1.3(P3.5) U5.5(SDA)
I2C_SDA_REG: R13.2 U1.35(P4.1) U2.2(SDA)
IMON_REG: C29.2 U2.16(IMON)
IN_HPD_DP0: R32.1 R36.2 U5.25(IN_HPD)
LED: R10.2 U1.2(P3.3)
M0+_P0: J4.12(ML_LANE_0P) R19.1
M0-_P0: J4.10(ML_LANE_0N) R20.1
M1+_P0: J4.9(ML_LANE_1P) R17.1
M1-_P0: J4.7(ML_LANE_1N) R18.1
M2+_P0: J4.6(ML_LANE_2P) R23.1
M2-_P0: J4.4(ML_LANE_2N) R21.1
M3+_P0: J4.3(ML_LANE_3P) R26.1
M3-_P0: J4.1(ML_LANE_3N) R25.1
PMG1S3_SWD_CLK: J2.4 U1.12(P1.1/SWD_CLK)
PMG1S3_SWD_IO: J2.5 U1.13(P1.2/SWD_IO)
RX1+_P0: C51.1 J5.B11(RX1+) R44.1 U4.5(I/O4) U4.6(NC4)
RX1-_P0: C50.1 J5.B10(RX1-) R45.1 U4.4(I/O3) U4.7(NC3)
RX2+_P0: C46.1 C47.1 J5.A10(RX2-) J5.A11(RX2+) R42.1 R43.1 U3.1(I/O1) U3.2(I/O2) U3.9(NC2) U3.10(NC1)
SBU1: J5.A8(SBU1) R22.2
SBU2: J5.B8(SBU2) R24.2
TX1+_P0: C49.1 J5.A2(TX1+) U4.2(I/O2) U4.9(NC2)
TX1-_P0: C48.1 J5.A3(TX1-) U4.1(I/O1) U4.10(NC1)
TX2+_P0: C44.1 C45.1 J5.B2(TX2+) J5.B3(TX2-) U3.4(I/O3) U3.5(I/O4) U3.6(NC4) U3.7(NC3)
TYPE-C-VBUS: C52.1 C53.2 D3.C(CATHODE) J5.A4(VBUS_1) J5.A9(VBUS_2) J5.B4(VBUS_3) J5.B9(VBUS_4) Q2.1(SOURCE1) Q2.2(SOURCE2) Q2.3(SOURCE3) Q6.2(D1) Q6.4(D2) U1.25(VBUS_OUT_NGDO) U1.31(VBUS-C)
USB2_VBUS_P0: C41.2 J3.1(VBUS)
USB_C_PWR: D7.A(ANODE) J6.1 Q5.2(D1) Q5.4(D2)
USB_P_PWR: C21.2 C22.2 C23.2 C25.2 C26.1 C27.2 Q4.5(DRAIN1) Q4.6(DRAIN2) Q4.7(DRAIN3) Q4.8(DRAIN4) R1.1 R2.1 R3.1 U1.38(CSP) USB_P_PWR.1
XRES: C24.2 J2.3 R39.1 SW1.1 SW1.2 U1.33(XRES)
N15123878: C19.1(NN_Pin) L1.1(NN_Pin) Q3.1(SOURCE1) Q3.2(SOURCE2) Q3.3(SOURCE3) U2.14(SW1)
N15123894: C20.2(NN_Pin) L1.2(NN_Pin) Q4.1(SOURCE1) Q4.2(SOURCE2) Q4.3(SOURCE3) U2.13(SW2)
N15124350: C19.2(NN_Pin) R4.1
N15124370: C20.1(NN_Pin) R5.1
N15124398: Q3.4(GATE) U2.18(HG1)
N15124434: Q4.4(GATE) U2.9(HG2)
N15124462: R2.2 U2.7(VOUT)
N15124466: C28.2 R3.2 R6.1
N15124528: R4.2 U2.19(BST1)
N15124532: R5.2 U2.8(BST2)
N15124650: C28.1 R6.2 R7.2 R8.1
N15124774: R9.2 U2.17(EN)
N15124816: C30.2 U2.10(VCC)
N15125170: D1.A(ANODE) J1.2
N15130096: C42.2 J3.6(STDB_SSTX+)
N15130104: C43.2 J3.5(STDB_SSTX-)
N15130234: J3.9(STDB_SSRX+) R15.1
N15130254: R15.2 U5.28(SSTXP)
N15130262: J3.8(STDB_SSRX-) R16.1
N15130282: R16.2 U5.27(SSTXN)
N15130306: C42.1 U5.24(SSRXP)
N15130330: C43.1 U5.23(SSRXN)
N15130334: C44.2 U5.20(TX2P)
N15130360: C45.2 U5.19(TX2N)
N15130386: C46.2 U5.16(RX2P)
N15130412: C47.2 U5.15(RX2N)
N15130458: C48.2 U5.12(TX1N)
N15130506: R17.2 U5.30(DP1P)
N15130510: C49.2 U5.11(TX1P)
N15130558: R18.2 U5.31(DP1N)
N15130562: C50.2 U5.8(RX1N)
N15130610: R19.2 U5.33(DP0P)
N15130614: C51.2 U5.7(RX1P)
N15130646: R20.2 U5.34(DP0N)
N15130698: R21.2 U5.36(DP2N)
N15130702: R22.1 U5.4(AUXSBU1)
N15130826: R23.2 U5.37(DP2P)
N15130830: R24.1 U5.3(AUXSBU2)
N15130860: R25.2 U5.39(DP3N)
N15130876: R26.2 U5.40(DP3P)
N15130880: R31.2 R35.1 U5.18(A2)
N15130912: R30.2 R34.1 U5.13(A1)
N15130952: R27.2 U5.1(AUXP)
N15130956: R29.2 R33.1 U5.9(A0)
N15130974: R28.2 U5.2(AUXN)
N15131244: J4.18(HotPlugDetect) R36.1
N15138150: Q1.5(DRAIN1) Q1.6(DRAIN2) Q1.7(DRAIN3) Q1.8(DRAIN4) Q2.5(DRAIN1) Q2.6(DRAIN2) Q2.7(DRAIN3) Q2.8(DRAIN4)
N15140813: D4.C(CATHODE) D7.C(CATHODE) R37.1
N15140817: C56.2 C57.2 D5.C(CATHODE) DC_PWR.1 R37.2 R50.1 U6.1(VIN)
N15140921: R57.1 U6.9(VCC)
N15140997: C55.1 L2.1 R52.1 U6.7(SW)
N15141009: C58.1 C59.2 C60.2 C61.2 C62.2 L2.2 R51.1 R53.1 U6.5(OUT)
N15141113: C58.2 R52.2 R55.1
N15141173: R50.2 R56.1 U6.12(EN)
N15141285: R57.2 U6.3(PG)
N15141305: R53.2 R55.2 R59.1 U6.11(FB)
N15141309: R58.1 U6.6(MODE)
N15142175: C65.2 C66.2 R60.2 R63.1 R64.1 U7.7(VIN)
N15142207: C67.1 L3.2 R61.1 R65.1 U7.4(OUT)
N15142409: LED2.A(ANODE) R62.2
N15142413: R63.2 U7.1(EN)
N15142451: R64.2 U7.8(PG)
N15142475: C67.2 R65.2 R66.1 U7.2(FB)
N15180587: LED3.A(ANODE) R10.1
N15182243: R7.1 U2.4(FB)
N15183154: Q7.3(DRAIN) R46.2
N15183747: C55.2 R49.1
N15183748: R49.2 U6.8(BST)
N15183749: L3.1 U7.6(SW)
N15183789: LED1.A(ANODE) R54.2
N15184116: J4.13(CONFIG1) R40.1
N15184117: J4.14(CONFIG2) R41.1

Not connected (* = marked no-connect by the designer): J4 20(DP_PWR)*; U1 1(P3.0)* 7(P5.0)* 8(P5.1)* 9(P5.2)* 10(P5.3)* 11(P5.5)* 15(P6.0)* 16(P6.1)* 17(P0.0)* 18(P6.2)* 19(P6.3)* 20(P1.4)* 21(P1.5)* 22(P1.6)* 39(D+)* 40(D-)* 45(P2.4)* 46(P2.3)* 47(P2.2)* 48(P2.1)*; U5 21(DCI_DAT)* 22(DCI_CLK)*; U6 4(NC)*

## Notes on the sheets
sheet 1
- PMG1-S3 (CYPM1311) DRP REFERENCE DESIGN
- CONTENTS
- PAGE
- DESCRIPTION
- 01
- TITLE & TABLE OF CONTENTS
- 02
- PMG1-S3 CONTROLLER
- 03
- STEP DOWN REGULTORS
- 04
- PD REGULATOR
- 05
- VBUS PROVIDER/CONSUMER FET AND TYPE-C CONNCETOR
- 06
- USB SUPERSPEED AND DISPLAY PORT MUX (Optional)
sheet 2
- VBUS PROVIDER/CONSUMER FET AND TYPE-C CONNCETOR
- SPR Source
- 5V,9V,15V,20V / 5A
- EPR Source
- 28V / 5A
- PROVIDER PATH LOAD SWITCH
- SPR Sink 5V - 20V
- EPR Sink 28V
- CONSUMER PATH LOAD SWITCH
sheet 3
- USB SUPERSPEED AND DISPLAY PORT MUX (OPTIONAL)
- ESD DT1240A-04LP
- For I2C
  Address
- I2C Slave Addess 7 BIT :  0x50
- USB SUPERSPEED AND DISPLAY PORT MUX (OPTIONAL)
sheet 4
- PD REGULATOR
sheet 5
- STEP DOWN REGULATORS
- DC/DC CONVERTER 5V,2.5A
- Step-Down Regulator - 3.3V/1.5A
sheet 6
- PMG1-S3 CONTROLLER
- DECOUPLING CAPACITORS
- USER LED
- VSYS AND VCONN_SRC
- SWD PROGRAMMING HEADER
- RESET BUTTON
